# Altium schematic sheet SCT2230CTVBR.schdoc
size 127 x 101 mm
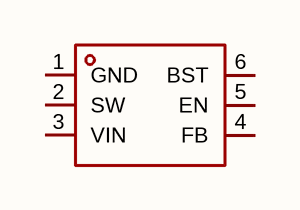
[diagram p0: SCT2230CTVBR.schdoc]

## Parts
U?  sct2230ctvbr  [TSOT-23-6_L2.9-W1.6-P0.95-LS2.8-BL]  (value not drawn)

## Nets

Not connected (* = marked no-connect by the designer): U? 1(GND) 2(SW) 3(VIN) 4(FB) 5(EN) 6(BST)

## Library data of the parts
U? = sct2230ctvbr: 功能类型:降压型;工作电压:4.2V~17V;输出电压:800mV~7V;输出电流:3A;输出类型:可调;; Manufacturer: SCT(芯洲科技); AddInBom: yes; ModelId: 2c4039b5b88644c1bda4b4ba9e971667; ModelName: TSOT-23-6_L2.9-W1.6-H1.1-LS2.8-P0.95; ModelTransform: 110.236,114.173,0,90,0,0,0,0,0; Function: 降压型; Output Current: 3A; Frequency - Switching: 750kHz; Synchronous Rectifier: 是; Number of Outputs: 1; Topology: 降压式; Quiescent Current: 135uA; Switch tube (built-in/external): 内置; Output Type: 可调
